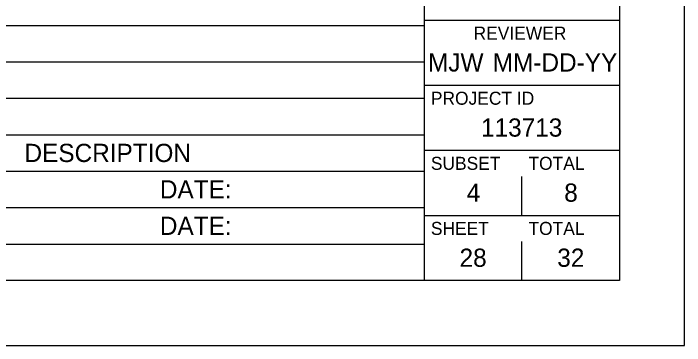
# Model space of a CAD drawing. Extents: x 0 to 34, y 0 to 22.
# Drawn here: x 28.84 to 34, y 0 to 2.55 of the extents above; entities that cross this region are included whole.
import ezdxf

# ---------------------------------------------------------------- set-up
doc = ezdxf.new("R2010")
doc.units = 0
for name, color, linetype in [('SH_Border', 7, 'Continuous'), ('SH_Cut_Line', 7, 'Continuous'), ('SH_Data', 7, 'Continuous'), ('SH_Text', 7, 'Continuous'), ('SN_P_Truss_Overhead', 7, 'Continuous')]:
    doc.layers.add(name, color=color, linetype=linetype)

msp = doc.modelspace()

# ---------------------------------------------------------------- linework, layer by layer
at = {"layer": 'SH_Border'}
for p, q in [((32, 0.5), (32, 21.5)), ((32, 2.5), (33.5, 2.5)), ((32, 2), (33.5, 2)), ((32, 1.5), (33.5, 1.5)), ((32, 1), (33.5, 1))]:
    msp.add_line(p, q, dxfattribs=at)
msp.add_lwpolyline([(1.5, 21.5), (33.5, 21.5), (33.5, 0.5), (1.5, 0.5)], close=True, dxfattribs=at)
at = {"layer": 'SH_Cut_Line'}
msp.add_lwpolyline([(0, 0), (34, 0), (34, 22), (0, 22)], close=True, dxfattribs=at)
at = {"layer": 'SH_Data'}
for p, q in [((32.75, 1), (32.75, 1.3)), ((32.75, 0.5), (32.75, 0.8)), ((32.375, 0.675), (32.375, 0.675))]:
    msp.add_line(p, q, dxfattribs=at)
at = {"layer": 'SH_Text'}
for p, q in [((25.1966, 2.46), (32, 2.46)), ((25.1966, 2.18), (32, 2.18)), ((25.1966, 1.9), (32, 1.9)), ((25.1966, 1.62), (32, 1.62)), ((25.1966, 1.34), (32, 1.34)), ((25.1966, 1.06), (32, 1.06)), ((25.1966, 0.78), (32, 0.78)), ((32, 0.5), (32, 0.5))]:
    msp.add_line(p, q, dxfattribs=at)

# ---------------------------------------------------------------- texts
at = {"layer": 'SH_Data'}
for s, height, p in [('REVIEWER', 0.1, (32.3783, 2.35)), ('MJW', 0.14, (32.0284, 2.105)), ('MM-DD-YY', 0.14, (32.5259, 2.105)), ('PROJECT ID', 0.1, (32.05, 1.85)), ('SUBSET', 0.1, (32.05, 1.35)), ('TOTAL', 0.1, (32.8, 1.35)), ('4', 0.14, (32.3254, 1.105)), ('8', 0.14, (33.075, 1.105)), ('SHEET', 0.1, (32.05, 0.85)), ('TOTAL', 0.1, (32.8, 0.85)), ('28', 0.14, (32.2706, 0.605)), ('32', 0.14, (33.0214, 0.605))]:
    msp.add_text(s, height=height, dxfattribs=at).set_placement(p)
at = {"layer": 'SH_Text'}
for s, p in [('DESCRIPTION', (28.9268, 1.41)), ('DATE:', (29.9673, 1.13)), ('DATE:', (29.9673, 0.85))]:
    msp.add_text(s, height=0.14, dxfattribs=at).set_placement(p)
at = {"layer": 'SN_P_Truss_Overhead'}
msp.add_text('113713', height=0.14, dxfattribs=at).set_placement((32.4355, 1.605))

doc.saveas('drawing.dxf')
